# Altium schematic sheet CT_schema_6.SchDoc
size 371 x 336 mm
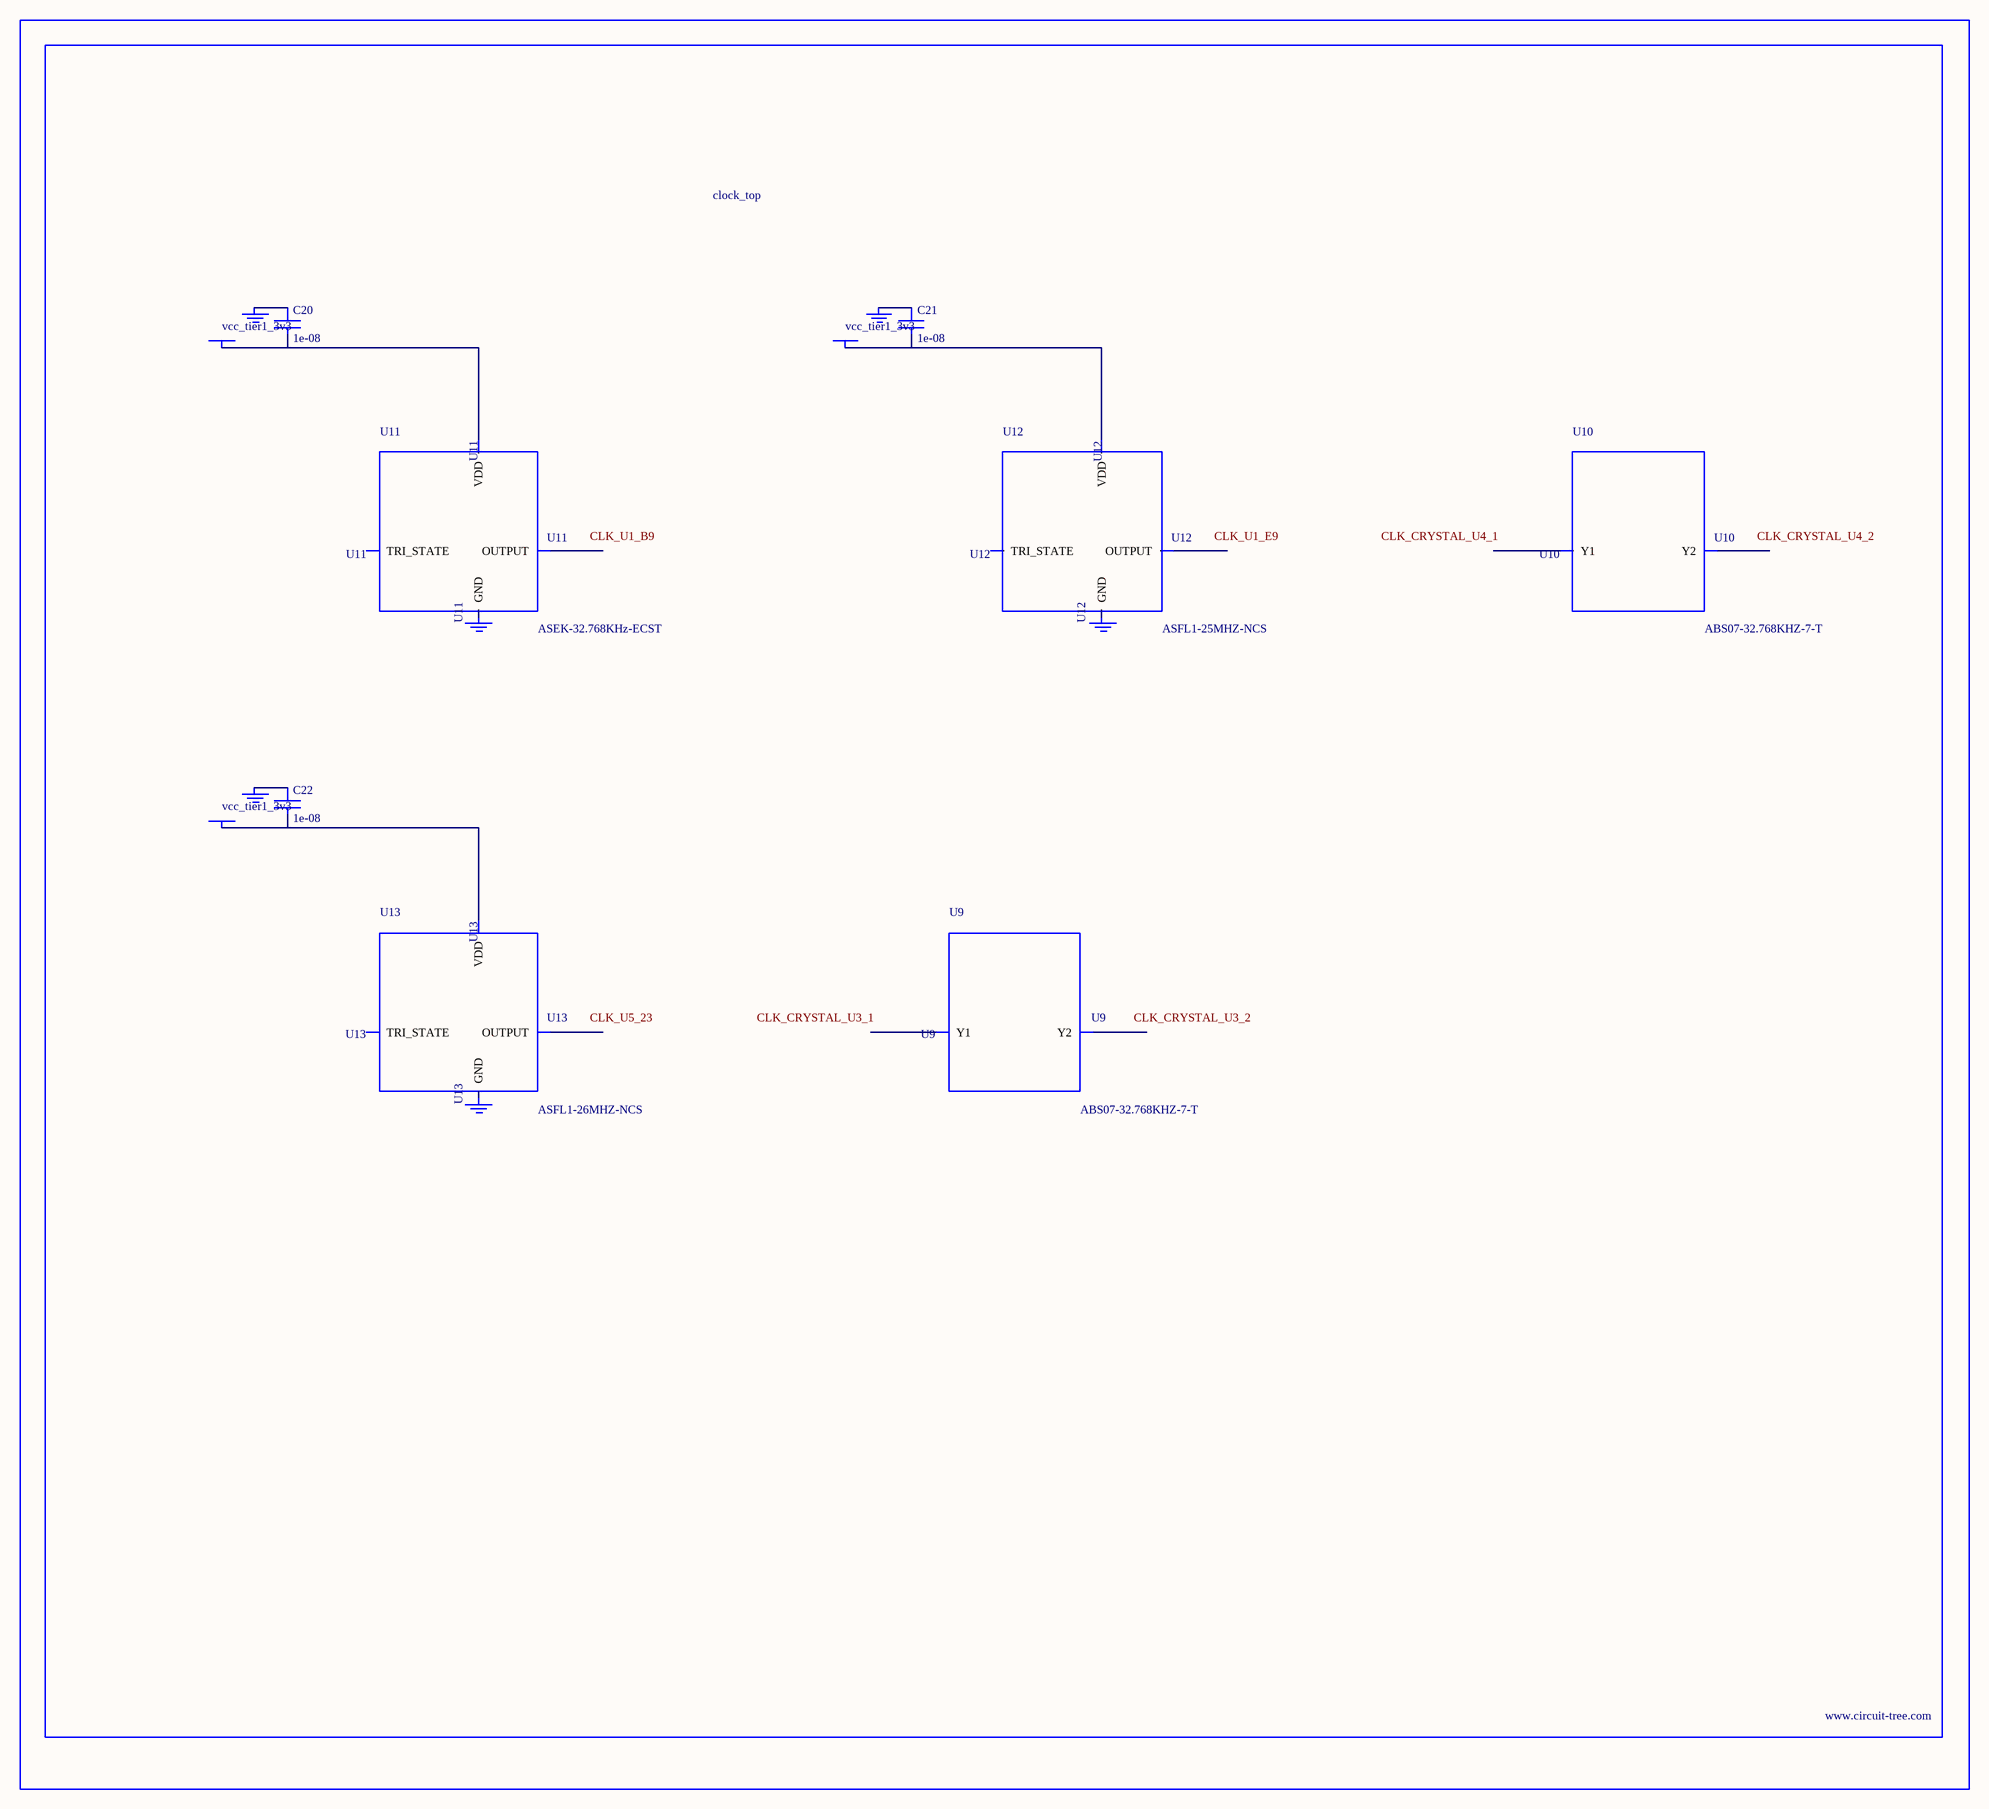
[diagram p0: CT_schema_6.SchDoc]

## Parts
BORDER5  (no value)
C20  1e-08  [C0402]
C21  1e-08  [C0402]
C22  1e-08  [C0402]
GND_INSTANCE_5_0  (no value)
GND_INSTANCE_5_1  (no value)
GND_INSTANCE_5_2  (no value)
GND_INSTANCE_5_3  (no value)
GND_INSTANCE_5_4  (no value)
GND_INSTANCE_5_5  (no value)
POWER_INSTANCE_5_0  vcc_tier1_3v3
POWER_INSTANCE_5_1  vcc_tier1_3v3
POWER_INSTANCE_5_2  vcc_tier1_3v3
U9  ABS07-32.768KHZ-7-T  [ABS07-32.768KHZ-7-T]
U10  ABS07-32.768KHZ-7-T  [ABS07-32.768KHZ-7-T]
U11  ASEK-32.768KHz-ECST  [ASEK]
U12  ASFL1-25MHZ-NCS  [ASFL1]
U13  ASFL1-26MHZ-NCS  [ASFL1]

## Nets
NetC20_1: C20.1 GND_INSTANCE_5_0.0(GND)
NetC20_2: C20.2 POWER_INSTANCE_5_0.0(PWR) U11.4(VDD)
NetC21_1: C21.1 GND_INSTANCE_5_2.0(GND)
NetC21_2: C21.2 POWER_INSTANCE_5_1.0(PWR) U12.4(VDD)
NetC22_1: C22.1 GND_INSTANCE_5_4.0(GND)
NetC22_2: C22.2 POWER_INSTANCE_5_2.0(PWR) U13.4(VDD)

Not connected (* = marked no-connect by the designer): GND_INSTANCE_5_1 0(GND); GND_INSTANCE_5_3 0(GND); GND_INSTANCE_5_5 0(GND); U9 1(Y1) 2(Y2); U10 1(Y1) 2(Y2); U11 1(TRI_STATE) 2(GND) 3(OUTPUT); U12 1(TRI_STATE) 2(GND) 3(OUTPUT); U13 1(TRI_STATE) 2(GND) 3(OUTPUT)

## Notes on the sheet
- Labels drawn without touching a wire or pin: CLK_CRYSTAL_U3_1, CLK_CRYSTAL_U3_2, CLK_CRYSTAL_U4_1, CLK_CRYSTAL_U4_2, CLK_U1_B9, CLK_U1_E9, CLK_U5_23

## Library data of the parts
BORDER5 = BORDER_PAGE5
C20-C22 = C0402C103K3RAC
GND_INSTANCE_5_0-GND_INSTANCE_5_5 = GND
POWER_INSTANCE_5_0-POWER_INSTANCE_5_2 = PWR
